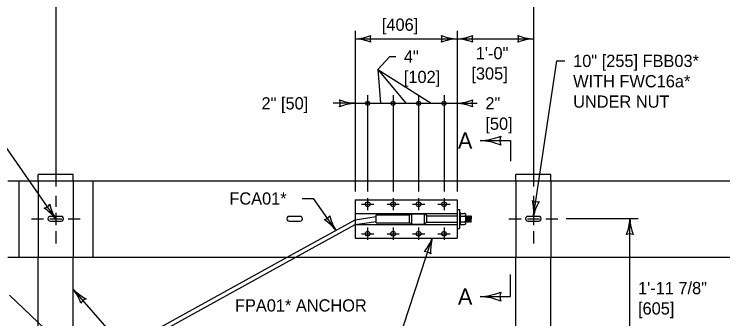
# Model space of a CAD drawing. Extents: x 49991.4 to 50021, y 49987.6 to 50011.4.
# Drawn here: x 50001.141 to 50004.618, y 49995.344 to 49996.841 of the extents above; entities that cross this region are included whole.
import ezdxf

# ---------------------------------------------------------------- set-up
doc = ezdxf.new("R2010")
doc.units = 0
for name, color, linetype in [('Level 1', 7, 'Continuous'), ('Level 2', 7, 'Continuous'), ('Level 3', 7, 'Continuous'), ('Level 4', 7, 'Continuous'), ('Level 5', 7, 'Continuous'), ('Level 6', 7, 'Continuous')]:
    doc.layers.add(name, color=color, linetype=linetype)

msp = doc.modelspace()

# ---------------------------------------------------------------- linework, layer by layer
at = {"layer": 'Level 1'}
for p, q in [((50001.2594, 49996.0223), (50001.2594, 49996.0535)), ((50001.431, 49996.0535), (50001.2594, 49996.0535)), ((50001.431, 49996.0223), (50001.431, 49996.0535)), ((50003.6032, 49996.0223), (50003.6032, 49996.0535)), ((50003.7748, 49996.0535), (50003.6032, 49996.0535)), ((50003.7748, 49996.0223), (50003.7748, 49996.0535)), ((50001.1097, 49996.0223), (50006.4116, 49996.0223)), ((50001.164, 49996.0223), (50001.164, 49995.6473)), ((50001.372, 49995.8477), (50001.3184, 49995.8477)), ((50002.5439, 49995.8477), (50002.4903, 49995.8477)), ((50003.7158, 49995.8477), (50003.6622, 49995.8477)), ((50001.3184, 49995.8247), (50001.372, 49995.8247)), ((50002.4903, 49995.8247), (50002.5439, 49995.8247)), ((50003.6622, 49995.8247), (50003.7158, 49995.8247)), ((50001.1097, 49995.6473), (50006.4116, 49995.6473)), ((50001.2594, 49995.1173), (50001.2594, 49995.6473)), ((50001.431, 49995.1175), (50001.431, 49995.6473)), ((50001.6293, 49995.177), (50002.4808, 49995.6473)), ((50001.6293, 49995.1536), (50002.5232, 49995.6473)), ((50003.6032, 49995.1175), (50003.6032, 49995.6473)), ((50003.7748, 49995.1175), (50003.7748, 49995.6473))]:
    msp.add_line(p, q, dxfattribs=at)
for centre in [(50002.8755, 49995.9073), (50003.0004, 49995.9074), (50003.1254, 49995.9074), (50003.2504, 49995.9074), (50002.8754, 49995.7622), (50003.0004, 49995.7622), (50003.1254, 49995.7622), (50003.2504, 49995.7622)]:
    msp.add_circle(centre, 0.0117, dxfattribs=at)
for centre, ratio, start_param, end_param in [((50001.3184, 49995.8362), 0.988923, 1.570796, 4.712389), ((50001.372, 49995.8362), 0.995211, 4.712389, 7.853982), ((50002.4903, 49995.8362), 0.988923, 1.570796, 4.712389), ((50002.5439, 49995.8362), 0.995211, 4.712389, 7.853982), ((50003.6622, 49995.8362), 0.988923, 1.570796, 4.712389), ((50003.7158, 49995.8362), 0.995211, 4.712389, 7.853982)]:
    msp.add_ellipse(centre, major_axis=(0.0116, 0), ratio=ratio, start_param=start_param, end_param=end_param, dxfattribs=at)
at = {"layer": 'Level 3'}
for p, q in [((50001.3453, 49997.2867), (50001.3452, 49995.9948)), ((50003.689, 49997.0368), (50003.689, 49995.9948)), ((50002.814, 49996.7596), (50002.814, 49995.9691)), ((50003.314, 49996.7596), (50003.314, 49995.9691)), ((50002.814, 49996.7196), (50003.314, 49996.7196)), ((50003.314, 49996.7196), (50003.689, 49996.7196)), ((50003.689, 49995.8477), (50003.8038, 49996.6115)), ((50003.8038, 49996.6115), (50003.8438, 49996.6115)), ((50002.9246, 49996.5695), (50002.938, 49996.403)), ((50002.9246, 49996.5695), (50003.0629, 49996.403)), ((50002.9246, 49996.5695), (50003.1879, 49996.403)), ((50002.8755, 49996.443), (50002.8755, 49995.9691)), ((50003.0004, 49996.443), (50003.0004, 49995.9691)), ((50003.1254, 49996.443), (50003.1254, 49995.9691)), ((50003.2504, 49996.443), (50003.2504, 49995.9691)), ((50002.814, 49996.403), (50002.7058, 49996.403)), ((50002.814, 49996.403), (50002.8755, 49996.403)), ((50002.8755, 49996.403), (50003.0004, 49996.403)), ((50003.0004, 49996.403), (50003.1254, 49996.403)), ((50003.1254, 49996.403), (50003.2504, 49996.403)), ((50003.2504, 49996.403), (50003.314, 49996.403)), ((50003.314, 49996.403), (50003.413, 49996.403)), ((50001.3452, 49995.8348), (50001.0256, 49996.2962)), ((50002.5533, 49995.9354), (50002.6103, 49995.9354)), ((50002.7195, 49995.7791), (50002.6103, 49995.9354)), ((50004.2021, 49995.8348), (50003.849, 49995.8348)), ((50004.1621, 49995.0551), (50004.1621, 49995.8348)), ((50003.0509, 49995.3101), (50003.1927, 49995.7413)), ((50001.9882, 49994.852), (50001.431, 49995.4894)), ((50001.1178, 49995.4611), (50001.389, 49995.2033))]:
    msp.add_line(p, q, dxfattribs=at)
msp.add_lwpolyline([(50002.9246, 49996.5695), (50002.9835, 49996.6327), (50003.013, 49996.6327)], dxfattribs=at)
for centre in [(50002.8755, 49996.403), (50003.0004, 49996.403), (50003.1254, 49996.403), (50003.2504, 49996.403)]:
    msp.add_circle(centre, 0.01, dxfattribs=at)
for centre, radius, start, end in [((50002.8025, 49996.9523), 0.233, 272.8273, 292.0772), ((50002.8048, 49996.4974), 0.2223, 67.456, 87.6395), ((50002.9422, 49996.7196), 0.0548, 162.1388, 197.8612), ((50003.3232, 49996.9417), 0.2223, 247.456, 267.6395), ((50003.1858, 49996.7196), 0.0548, 342.1388, 17.8612), ((50003.3255, 49996.4868), 0.233, 92.8273, 112.0772), ((50003.3025, 49996.9523), 0.233, 272.8273, 292.0772), ((50003.3048, 49996.4974), 0.2223, 67.456, 87.6395), ((50003.4422, 49996.7196), 0.0548, 162.1388, 197.8612), ((50003.6982, 49996.9417), 0.2223, 247.456, 267.6395), ((50003.5608, 49996.7196), 0.0548, 342.1388, 17.8612), ((50003.7005, 49996.4868), 0.233, 92.8273, 112.0772), ((50002.8232, 49996.6252), 0.2223, 247.456, 267.6395), ((50002.6858, 49996.403), 0.0548, 342.1388, 17.8612), ((50002.8255, 49996.1703), 0.233, 92.8273, 112.0772), ((50003.3025, 49996.6357), 0.233, 272.8273, 292.0772), ((50003.3048, 49996.1809), 0.2223, 67.456, 87.6395), ((50003.4422, 49996.403), 0.0548, 162.1388, 197.8612), ((50003.4115, 49996.5301), 0.3107, 272.8273, 292.0772), ((50003.5978, 49996.2198), 0.073, 162.1388, 197.8612), ((50003.4146, 49995.9237), 0.2964, 67.456, 87.6395), ((50003.7081, 49995.9745), 0.0548, 243.5896, 279.312), ((50003.4572, 49995.8709), 0.233, 354.2781, 13.5279), ((50003.9073, 49995.8056), 0.2223, 148.9068, 169.0903), ((50001.2727, 49995.9406), 0.0548, 286.5935, 322.3158), ((50001.1598, 49995.6937), 0.233, 37.2819, 56.5318), ((50001.5335, 49995.953), 0.2223, 191.9106, 212.0941), ((50002.6453, 49995.8837), 0.0548, 287.4985, 323.2209), ((50002.9059, 49995.9002), 0.2223, 192.8157, 212.9992), ((50002.5363, 49995.6351), 0.233, 38.187, 57.4369), ((50003.94, 49995.844), 0.2223, 337.456, 357.6395), ((50004.3948, 49995.8463), 0.233, 182.8273, 202.0772), ((50002.9845, 49995.8194), 0.2223, 319.2573, 339.4408), ((50003.4174, 49995.6796), 0.233, 164.6286, 183.8785), ((50004.1621, 49995.7066), 0.0548, 72.1388, 107.8612), ((50003.1527, 49995.6195), 0.0548, 53.9401, 89.6625), ((50001.2577, 49995.3501), 0.2223, 18.6157, 38.7992), ((50001.5986, 49995.6512), 0.233, 223.987, 243.2368), ((50003.4115, 49995.7635), 0.3107, 272.8273, 292.0772), ((50003.5978, 49995.4532), 0.073, 162.1388, 197.8612), ((50001.5154, 49995.3928), 0.0548, 113.2985, 149.0208), ((50003.4146, 49995.1571), 0.2964, 67.456, 87.6395)]:
    msp.add_arc(centre, radius, start, end, dxfattribs=at)
at = {"layer": 'Level 4'}
for p, q in [((50001.2594, 49996.0223), (50001.2594, 49995.6473)), ((50001.431, 49996.0223), (50001.431, 49995.6473)), ((50001.5264, 49996.0223), (50001.5264, 49995.6473)), ((50003.6032, 49996.0223), (50003.6032, 49995.6473)), ((50003.7748, 49996.0223), (50003.7748, 49995.6473)), ((50002.814, 49995.9291), (50002.814, 49995.7413)), ((50002.814, 49995.9291), (50003.314, 49995.9291)), ((50003.314, 49995.9291), (50003.314, 49995.7413)), ((50003.314, 49995.8817), (50003.3258, 49995.8817)), ((50003.3258, 49995.8817), (50003.3258, 49995.7879)), ((50002.814, 49995.8625), (50003.314, 49995.8625)), ((50002.814, 49995.8313), (50002.9172, 49995.8466)), ((50002.9172, 49995.8154), (50002.9172, 49995.8544)), ((50002.9172, 49995.8544), (50003.0813, 49995.8544)), ((50003.0813, 49995.8544), (50003.093, 49995.8603)), ((50003.0813, 49995.8154), (50003.0813, 49995.8544)), ((50003.093, 49995.8603), (50003.1538, 49995.8603)), ((50003.093, 49995.8095), (50003.093, 49995.8603)), ((50003.1653, 49995.8505), (50003.1538, 49995.8603)), ((50003.1538, 49995.8095), (50003.1538, 49995.8603)), ((50003.1653, 49995.8505), (50003.314, 49995.8505)), ((50003.1653, 49995.8193), (50003.1653, 49995.8505)), ((50003.3302, 49995.8661), (50003.3258, 49995.8661)), ((50003.3302, 49995.8515), (50003.3258, 49995.8515)), ((50003.3302, 49995.8661), (50003.3302, 49995.8037)), ((50003.3302, 49995.8622), (50003.3509, 49995.8622)), ((50003.3302, 49995.8486), (50003.3509, 49995.8486)), ((50003.3576, 49995.8144), (50003.3576, 49995.8553)), ((50003.3579, 49995.8505), (50003.3576, 49995.8454)), ((50003.3576, 49995.8502), (50003.3579, 49995.8505)), ((50003.3594, 49995.8486), (50003.3579, 49995.8505)), ((50003.3594, 49995.8486), (50003.3579, 49995.8193)), ((50003.3594, 49995.8486), (50003.361, 49995.8505)), ((50003.361, 49995.8505), (50003.3594, 49995.8212)), ((50003.3625, 49995.8486), (50003.361, 49995.8505)), ((50003.3625, 49995.8486), (50003.361, 49995.8193)), ((50003.3625, 49995.8486), (50003.3641, 49995.8505)), ((50003.3641, 49995.8505), (50003.3625, 49995.8212)), ((50003.3656, 49995.8486), (50003.3641, 49995.8505)), ((50003.3656, 49995.8486), (50003.3641, 49995.8193)), ((50003.3656, 49995.8486), (50003.3672, 49995.8505)), ((50003.3672, 49995.8505), (50003.3656, 49995.8212)), ((50003.3687, 49995.8486), (50003.3672, 49995.8505)), ((50003.3687, 49995.8486), (50003.3672, 49995.8193)), ((50003.3687, 49995.8486), (50003.3702, 49995.8505)), ((50003.3702, 49995.8505), (50003.3687, 49995.8212)), ((50003.3717, 49995.8486), (50003.3702, 49995.8505)), ((50003.3717, 49995.8486), (50003.3702, 49995.8193)), ((50003.3717, 49995.8486), (50003.3733, 49995.8505)), ((50003.3733, 49995.8505), (50003.3717, 49995.8212)), ((50003.3748, 49995.8486), (50003.3733, 49995.8505)), ((50003.3748, 49995.8486), (50003.3733, 49995.8193)), ((50003.3748, 49995.8486), (50003.3764, 49995.8505)), ((50003.3764, 49995.8505), (50003.3748, 49995.8212)), ((50003.3779, 49995.8486), (50003.3764, 49995.8505)), ((50003.3779, 49995.8486), (50003.3764, 49995.8193)), ((50003.3779, 49995.8486), (50003.3795, 49995.8505)), ((50003.3795, 49995.8505), (50003.3779, 49995.8212)), ((50003.381, 49995.8486), (50003.3795, 49995.8505)), ((50003.381, 49995.8486), (50003.3795, 49995.8193)), ((50003.3825, 49995.8505), (50003.381, 49995.8212)), ((50003.381, 49995.8486), (50003.3825, 49995.8505)), ((50003.384, 49995.8486), (50003.3825, 49995.8505)), ((50003.384, 49995.8486), (50003.3825, 49995.8193)), ((50003.384, 49995.8212), (50003.384, 49995.8486)), ((50002.4808, 49995.6473), (50002.814, 49995.8313)), ((50002.814, 49995.8079), (50002.9172, 49995.8232)), ((50002.9172, 49995.8154), (50003.0813, 49995.8154)), ((50003.093, 49995.8095), (50003.0813, 49995.8154)), ((50003.093, 49995.8095), (50003.1538, 49995.8095)), ((50003.1653, 49995.8193), (50003.1538, 49995.8095)), ((50003.1653, 49995.8193), (50003.314, 49995.8193)), ((50003.3302, 49995.8183), (50003.3258, 49995.8183)), ((50003.3302, 49995.8213), (50003.3508, 49995.8213)), ((50003.3579, 49995.8193), (50003.3576, 49995.8197)), ((50003.3579, 49995.8193), (50003.3594, 49995.8212)), ((50003.361, 49995.8193), (50003.3594, 49995.8212)), ((50003.361, 49995.8193), (50003.3625, 49995.8212)), ((50003.3641, 49995.8193), (50003.3625, 49995.8212)), ((50003.3641, 49995.8193), (50003.3656, 49995.8212)), ((50003.3672, 49995.8193), (50003.3656, 49995.8212)), ((50003.3672, 49995.8193), (50003.3687, 49995.8212)), ((50003.3702, 49995.8193), (50003.3687, 49995.8212)), ((50003.3702, 49995.8193), (50003.3717, 49995.8212)), ((50003.3733, 49995.8193), (50003.3717, 49995.8212)), ((50003.3733, 49995.8193), (50003.3748, 49995.8212)), ((50003.3764, 49995.8193), (50003.3748, 49995.8212)), ((50003.3764, 49995.8193), (50003.3779, 49995.8212)), ((50003.3795, 49995.8193), (50003.3779, 49995.8212)), ((50003.3795, 49995.8193), (50003.381, 49995.8212)), ((50003.3825, 49995.8193), (50003.381, 49995.8212)), ((50003.3825, 49995.8193), (50003.384, 49995.8212)), ((50002.5232, 49995.6473), (50002.814, 49995.8079)), ((50002.814, 49995.8079), (50003.314, 49995.8079)), ((50003.314, 49995.7879), (50003.3258, 49995.7879)), ((50003.3302, 49995.8037), (50003.3258, 49995.8037)), ((50003.3302, 49995.8076), (50003.3508, 49995.8076)), ((50002.814, 49995.7413), (50003.314, 49995.7413))]:
    msp.add_line(p, q, dxfattribs=at)
for centre, start, end in [((50003.3508, 49995.8419), 0, 90), ((50003.3509, 49995.8555), 358.4089, 90), ((50003.3509, 49995.8554), 270, 360), ((50003.3508, 49995.8281), 270, 360), ((50003.3508, 49995.8146), 358.3028, 90), ((50003.3508, 49995.8144), 270, 360)]:
    msp.add_arc(centre, 0.00675, start, end, dxfattribs=at)
at = {"layer": 'Level 5'}
for p, q in [((50001.3452, 49995.9477), (50001.3452, 49995.8948)), ((50002.8755, 49995.9373), (50002.8755, 49995.8773)), ((50003.0004, 49995.9374), (50003.0004, 49995.8774)), ((50003.1254, 49995.9374), (50003.1254, 49995.8774)), ((50003.2504, 49995.9374), (50003.2504, 49995.8774)), ((50003.689, 49995.9477), (50003.689, 49995.8948)), ((50002.8455, 49995.9073), (50002.9055, 49995.9073)), ((50002.9704, 49995.9074), (50003.0304, 49995.9074)), ((50003.0954, 49995.9074), (50003.1554, 49995.9074)), ((50003.2204, 49995.9074), (50003.2804, 49995.9074)), ((50001.3452, 49995.8648), (50001.3452, 49995.8048)), ((50003.689, 49995.8648), (50003.689, 49995.8048)), ((50001.2252, 49995.8348), (50001.2852, 49995.8348)), ((50001.3152, 49995.8348), (50001.3752, 49995.8348)), ((50001.4052, 49995.8348), (50001.4652, 49995.8348)), ((50003.569, 49995.8348), (50003.629, 49995.8348)), ((50003.659, 49995.8348), (50003.719, 49995.8348)), ((50003.749, 49995.8348), (50003.809, 49995.8348)), ((50001.3452, 49995.7748), (50001.3452, 49995.7148)), ((50002.8754, 49995.7922), (50002.8754, 49995.7322)), ((50003.0004, 49995.7922), (50003.0004, 49995.7322)), ((50003.1254, 49995.7922), (50003.1254, 49995.7322)), ((50003.2504, 49995.7922), (50003.2504, 49995.7322)), ((50003.689, 49995.7748), (50003.689, 49995.7148)), ((50002.8454, 49995.7622), (50002.9054, 49995.7622)), ((50002.9704, 49995.7622), (50003.0304, 49995.7622)), ((50003.0954, 49995.7622), (50003.1554, 49995.7622)), ((50003.2204, 49995.7622), (50003.2804, 49995.7622))]:
    msp.add_line(p, q, dxfattribs=at)
at = {"layer": 'Level 6'}
for p, q in [((50003.4268, 49996.2198), (50003.5768, 49996.2198)), ((50003.5768, 49996.2198), (50003.5768, 49996.1185)), ((50003.5768, 49995.4532), (50003.5768, 49995.5627)), ((50003.4268, 49995.4532), (50003.5768, 49995.4532))]:
    msp.add_line(p, q, dxfattribs=at)

# ---------------------------------------------------------------- texts
at = {"layer": 'Level 2'}
for s, height, p in [('[406]', 0.06, (50002.9452, 49996.7596)), ('1\'-0"', 0.06, (50003.4061, 49996.6196)), ('4"', 0.06, (50003.053, 49996.6027)), ('10" [255] FBB03*', 0.06, (50003.8838, 49996.5815)), ('[305]', 0.06, (50003.3844, 49996.5196)), ('[102]', 0.06, (50003.053, 49996.5027)), ('WITH FWC16a*', 0.06, (50003.8838, 49996.4815)), ('2" [50]', 0.06, (50002.3547, 49996.373)), ('UNDER NUT', 0.06, (50003.8838, 49996.3815)), ('2"', 0.06, (50003.453, 49996.373)), ('[50]', 0.06, (50003.453, 49996.273)), ('A', 0.08, (50003.3181, 49996.1798)), ('FCA01*', 0.06, (50002.1969, 49995.9054)), ('1\'-11 7/8"', 0.06, (50004.2021, 49995.4653)), ('A', 0.08, (50003.3181, 49995.4132)), ('FPA01* ANCHOR', 0.06, (50002.2245, 49995.3801)), ('[605]', 0.06, (50004.2021, 49995.3653))]:
    msp.add_text(s, height=height, dxfattribs=at).set_placement(p)

doc.saveas('drawing.dxf')
